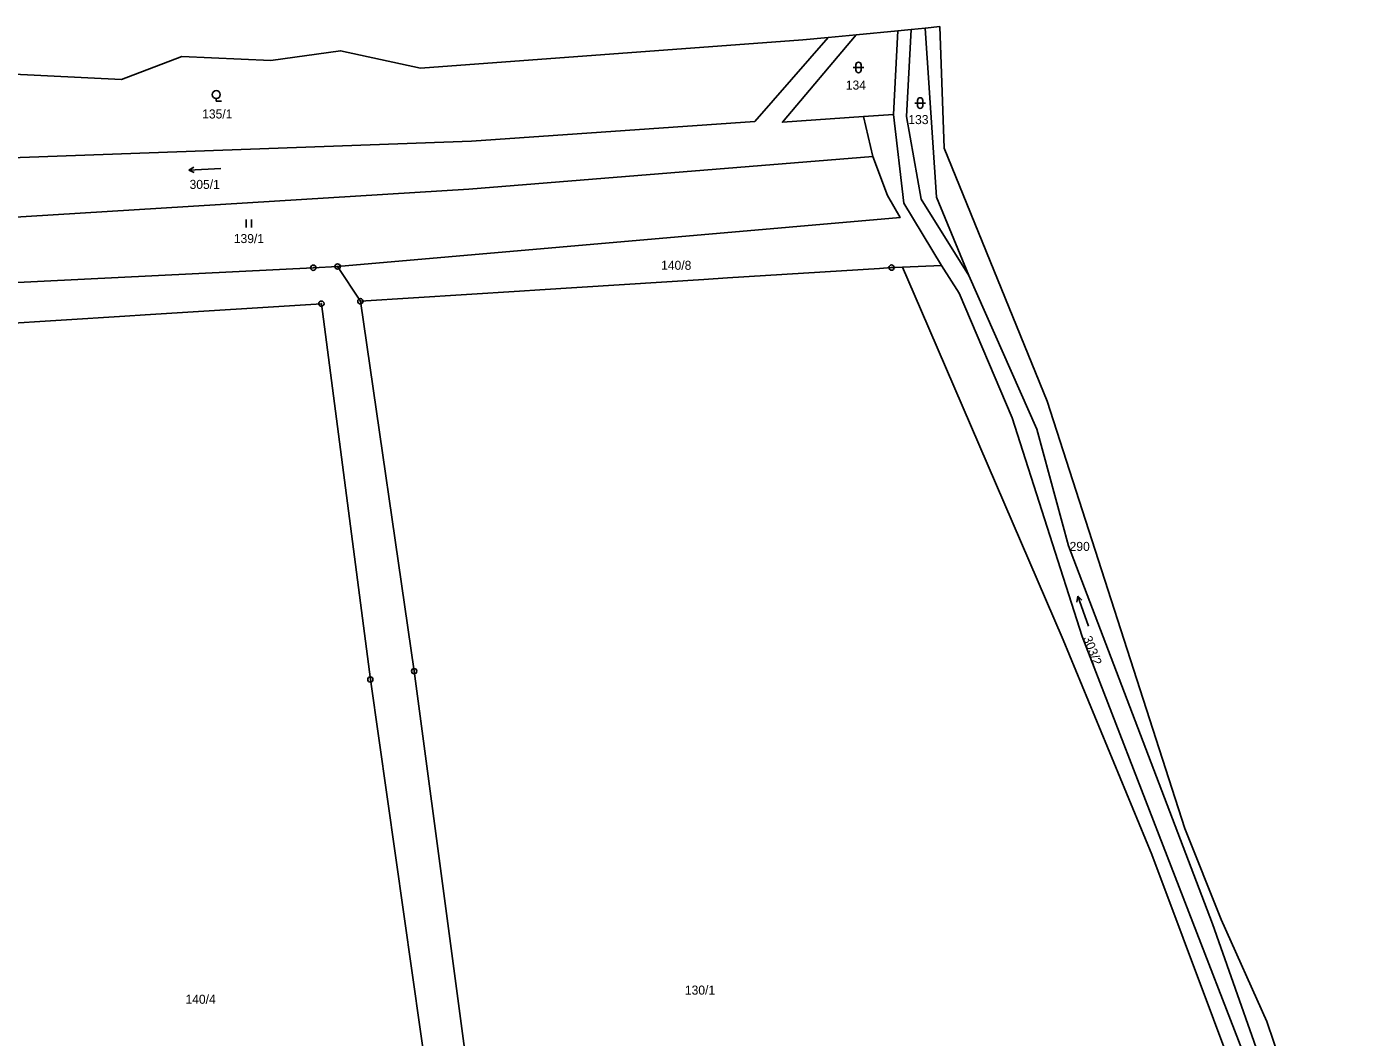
# Model space of a CAD drawing. Extents: x -779723 to -777378, y -1011169 to -1009297.
# Drawn here: x -779400.3 to -779149.8, y -1009527.9 to -1009337.8 of the extents above; entities that cross this region are included whole.
import ezdxf

# ---------------------------------------------------------------- set-up
doc = ezdxf.new("R2010")
doc.units = 0
for name, color, linetype in [('Hranice parcel', 7, 'Continuous'), ('Parcelní čísla', 7, 'Continuous'), ('Značky bodu BP', 7, 'Continuous'), ('Značky kultur', 7, 'Continuous')]:
    doc.layers.add(name, color=color, linetype=linetype)

msp = doc.modelspace()

# ---------------------------------------------------------------- linework, layer by layer
at = {"layer": 'Hranice parcel'}
for p, q in [((-779236.43, -1009338.55), (-779244.29, -1009339.29)), ((-779237.28, -1009354.3), (-779236.43, -1009338.55)), ((-779233.94, -1009338.31), (-779236.43, -1009338.55)), ((-779231.28, -1009338.06), (-779233.94, -1009338.31)), ((-779228.54, -1009337.77), (-779231.28, -1009338.06)), ((-779227.74, -1009360.66), (-779228.54, -1009337.77)), ((-779254.3, -1009340.24), (-779326.21, -1009345.59)), ((-779249.55, -1009339.79), (-779254.3, -1009340.24)), ((-779244.29, -1009339.29), (-779249.55, -1009339.79)), ((-779242.88, -1009354.69), (-779237.28, -1009354.3)), ((-779242.88, -1009354.69), (-779241.15, -1009362.19)), ((-779337.54, -1009389.43), (-779341.82, -1009382.9)), ((-779228.25, -1009382.68), (-779235.58, -1009383))]:
    msp.add_line(p, q, dxfattribs=at)
for points in [[(-779233.94, -1009338.31), (-779234.82, -1009354.68), (-779232.07, -1009370.22), (-779223.11, -1009384.6)], [(-779223.11, -1009384.6), (-779229.17, -1009369.86), (-779231.28, -1009338.06)], [(-779497.98, -1009365.2), (-779475.7, -1009360.83), (-779449.04, -1009360.59), (-779404.99, -1009362.49), (-779316.63, -1009359.34), (-779263.37, -1009355.64), (-779249.55, -1009339.79)], [(-779244.29, -1009339.29), (-779258.15, -1009355.75), (-779242.88, -1009354.69)], [(-779326.21, -1009345.59), (-779341.26, -1009342.31), (-779354.35, -1009344.13), (-779371.14, -1009343.37), (-779382.46, -1009347.72), (-779403.99, -1009346.62)], [(-779228.25, -1009382.68), (-779235.31, -1009370.99), (-779237.28, -1009354.3)], [(-779182.47, -1009488.62), (-779208.38, -1009408.24), (-779227.74, -1009360.66)], [(-779241.15, -1009362.19), (-779317.11, -1009368.37), (-779489.81, -1009378.99)], [(-779341.82, -1009382.9), (-779236.03, -1009373.7), (-779238.42, -1009369.55), (-779241.15, -1009362.19)], [(-779483.07, -1009390.37), (-779464.1, -1009388.97), (-779346.39, -1009383.13), (-779341.82, -1009382.9)], [(-779235.58, -1009383), (-779236.97, -1009383.06), (-779237.63, -1009383.1), (-779239.91, -1009383.25), (-779268.48, -1009385.06), (-779272.95, -1009385.34), (-779303.79, -1009387.29), (-779307.58, -1009387.53), (-779337.54, -1009389.43)], [(-779235.58, -1009383), (-779232.2, -1009390.85), (-779205.37, -1009453.16), (-779188.66, -1009493.49), (-779171.2, -1009540.24), (-779170.52, -1009548.81)], [(-779163.12, -1009646.01), (-779164.71, -1009604.51), (-779164.66, -1009568.35), (-779168.29, -1009539.04), (-779201.76, -1009452.52), (-779214.97, -1009411.37), (-779224.93, -1009387.94), (-779228.25, -1009382.68)], [(-779223.11, -1009384.6), (-779210.32, -1009413.49), (-779204.35, -1009435.45), (-779177.26, -1009506.55), (-779165.16, -1009540.9), (-779161.94, -1009568.71), (-779161.85, -1009601.99), (-779160.14, -1009644.48), (-779149.83, -1009664.35)], [(-779492.33, -1009399.26), (-779409.63, -1009394.01), (-779405.87, -1009393.77), (-779381.86, -1009392.24), (-779377.99, -1009391.99), (-779344.87, -1009389.89), (-779335.66, -1009460.59), (-779321.52, -1009559.92), (-779305.69, -1009671.4), (-779293.25, -1009755.59), (-779289.47, -1009768.49)], [(-779337.54, -1009389.43), (-779327.41, -1009459.02), (-779314.12, -1009558.7), (-779297.53, -1009670.16), (-779287.8, -1009735.34), (-779287.02, -1009740.57), (-779284.93, -1009754.6), (-779282.33, -1009763.99)], [(-779161.79, -1009540.47), (-779167.06, -1009524.91), (-779175.62, -1009505.77), (-779182.47, -1009488.62)]]:
    msp.add_lwpolyline(points, dxfattribs=at)
at = {"layer": 'Značky bodu BP'}
for centre, radius in [((-779346.39, -1009383.13), 0.5), ((-779346.39, -1009383.13), 0.0303), ((-779341.82, -1009382.9), 0.5), ((-779341.82, -1009382.9), 0.0303), ((-779237.63, -1009383.1), 0.5), ((-779237.63, -1009383.1), 0.0303), ((-779337.54, -1009389.43), 0.5), ((-779344.87, -1009389.89), 0.5), ((-779344.87, -1009389.89), 0.0303), ((-779337.54, -1009389.43), 0.0303), ((-779327.41, -1009459.02), 0.5), ((-779327.41, -1009459.02), 0.0303), ((-779335.66, -1009460.59), 0.5), ((-779335.66, -1009460.59), 0.0303)]:
    msp.add_circle(centre, radius, dxfattribs=at)
at = {"layer": 'Značky kultur'}
for p, q in [((-779244.84, -1009345.45), (-779242.84, -1009345.45)), ((-779244.34, -1009344.95), (-779244.34, -1009345.95)), ((-779243.34, -1009345.95), (-779243.34, -1009344.95)), ((-779364.63, -1009351.3), (-779364.63, -1009351.8)), ((-779364.63, -1009351.8), (-779363.63, -1009351.8)), ((-779233.24, -1009352.15), (-779231.24, -1009352.15)), ((-779232.74, -1009351.65), (-779232.74, -1009352.65)), ((-779231.74, -1009352.65), (-779231.74, -1009351.65)), ((-779369.78, -1009364.79), (-779368.83, -1009364.24)), ((-779363.79, -1009364.47), (-779369.78, -1009364.79)), ((-779369.78, -1009364.79), (-779368.78, -1009365.24)), ((-779359, -1009375.54), (-779359, -1009374.04)), ((-779358, -1009375.54), (-779358, -1009374.04)), ((-779202.62, -1009444.94), (-779202.76, -1009446.03)), ((-779200.57, -1009450.58), (-779202.62, -1009444.94)), ((-779202.62, -1009444.94), (-779201.82, -1009445.69))]:
    msp.add_line(p, q, dxfattribs=at)
msp.add_circle((-779364.63, -1009350.55), 0.75, dxfattribs=at)
for centre, start, end in [((-779243.84, -1009344.95), 0, 180), ((-779243.84, -1009345.95), 180, 359.9879), ((-779232.24, -1009351.65), 0, 180), ((-779232.24, -1009352.65), 180, 359.9879)]:
    msp.add_arc(centre, 0.5, start, end, dxfattribs=at)

# ---------------------------------------------------------------- texts
at = {"layer": 'Parcelní čísla'}
for s, p in [('134', (-779246.24, -1009349.62)), ('135/1', (-779367.29, -1009355.05)), ('133', (-779234.47, -1009356.11)), ('305/1', (-779369.66, -1009368.3)), ('139/1', (-779361.34, -1009378.49)), ('140/8', (-779280.97, -1009383.52)), ('290', (-779204.14, -1009436.41)), ('130/1', (-779276.5, -1009519.88)), ('140/4', (-779370.43, -1009521.6))]:
    msp.add_text(s, height=1.7, dxfattribs=at).set_placement(p)
msp.add_text('303/2', height=1.7, rotation=291, dxfattribs=at).set_placement((-779201.64, -1009452.78))

doc.saveas('drawing.dxf')
